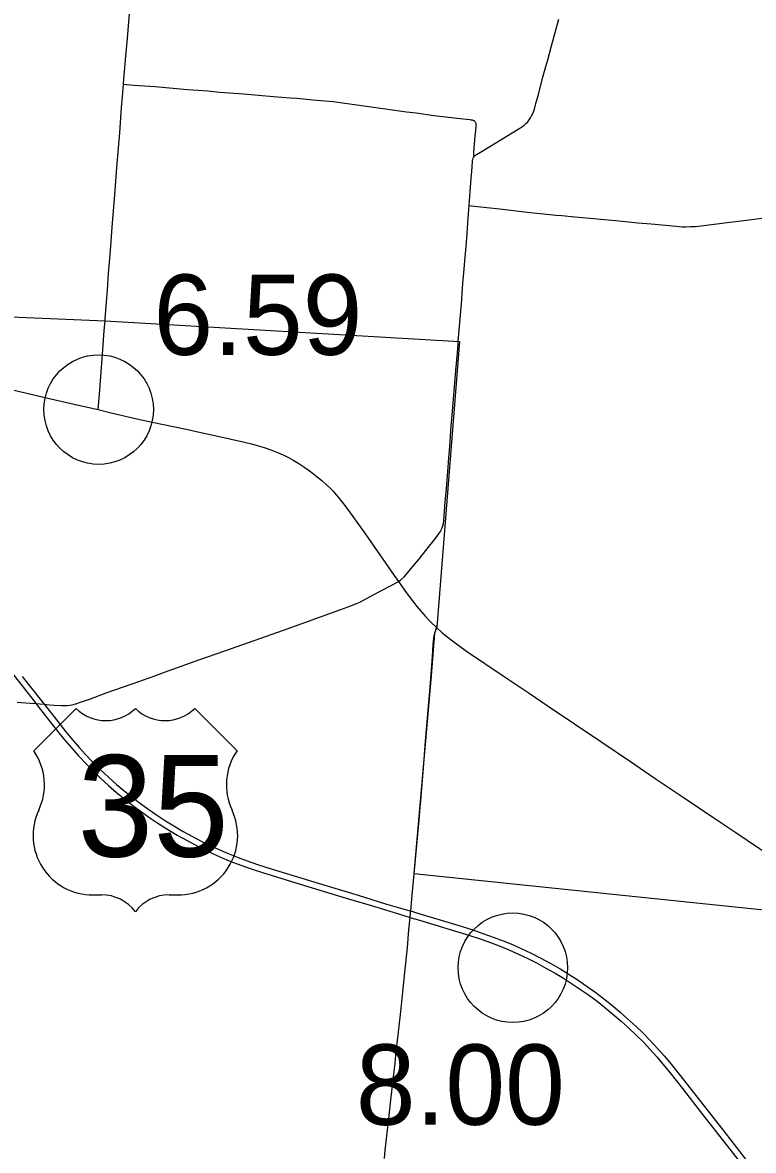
# Model space of a CAD drawing. Extents: x 1597222 to 1925846, y 496284 to 911751.
# Drawn here: x 1667359 to 1677369, y 576766 to 592215 of the extents above; entities that cross this region are included whole.
import ezdxf

# ---------------------------------------------------------------- set-up
doc = ezdxf.new("R2010")
doc.units = 0
for name, color, linetype in [('Default', 7, 'Continuous'), ('GM_X_County_Road', 7, 'Continuous'), ('GM_X_State_Route', 7, 'Continuous'), ('GM_X_Township', 7, 'Continuous'), ('GM_X_Township_Road', 7, 'Continuous'), ('GM_X_US_Route', 7, 'Continuous'), ('GM_X_US_Shield', 7, 'Continuous')]:
    doc.layers.add(name, color=color, linetype=linetype)

msp = doc.modelspace()

# ---------------------------------------------------------------- linework, layer by layer
at = {"layer": 'Default'}
for centre in [(1668401, 586914), (1668401, 586914), (1674074, 579269)]:
    msp.add_circle(centre, 750, dxfattribs=at)
at = {"layer": 'GM_X_County_Road'}
for points in [[(1673543, 590381), (1673551, 590389), (1673561, 590398), (1673574, 590408), (1673631, 590442), (1673841, 590569), (1674149, 590757), (1674204, 590793), (1674230, 590812), (1674254, 590834), (1674277, 590857), (1674297, 590882), (1674315, 590909), (1674331, 590937), (1674352, 590981), (1674369, 591027), (1674391, 591105), (1674424, 591232), (1674481, 591455), (1674498, 591518), (1674525, 591613), (1674552, 591707), (1674605, 591897), (1674704, 592261)], [(1673477, 589710), (1673491, 589899), (1673503, 590079), (1673510, 590177), (1673515, 590242), (1673520, 590308), (1673521, 590325), (1673525, 590341), (1673530, 590358), (1673535, 590369), (1673543, 590381)], [(1673326, 587848), (1673339, 588003), (1673370, 588363), (1673391, 588641), (1673407, 588837), (1673417, 588951), (1673433, 589147), (1673447, 589327), (1673459, 589474), (1673473, 589654), (1673477, 589710)], [(1673477, 589710), (1673508, 589707), (1673718, 589682), (1673897, 589662), (1674272, 589620), (1674582, 589588), (1674663, 589579), (1674744, 589572), (1674923, 589555), (1675135, 589535), (1675331, 589518), (1675478, 589504), (1675657, 589486), (1675787, 589473), (1675967, 589457), (1676309, 589426), (1676391, 589419), (1676440, 589418), (1676506, 589420), (1676572, 589424), (1676653, 589433), (1677011, 589478), (1677239, 589505), (1677483, 589534)], [(1673117, 585324), (1673123, 585356), (1673127, 585388), (1673148, 585650), (1673163, 585830), (1673187, 586124), (1673198, 586254), (1673206, 586352), (1673215, 586467), (1673226, 586630), (1673242, 586843), (1673260, 587055), (1673292, 587448), (1673314, 587693), (1673323, 587811), (1673326, 587848)], [(1668393, 586915), (1668573, 586871), (1668925, 586789), (1669133, 586744), (1669598, 586644), (1669759, 586610), (1670031, 586550), (1670400, 586469), (1670495, 586446), (1670574, 586424), (1670668, 586395), (1670760, 586362), (1670852, 586326), (1670927, 586294), (1671000, 586258), (1671072, 586218), (1671142, 586176), (1671224, 586121), (1671304, 586064), (1671395, 585995), (1671458, 585943), (1671519, 585888), (1671566, 585842), (1671611, 585795), (1671676, 585721), (1671738, 585646), (1671788, 585581), (1671884, 585448), (1672054, 585206), (1672262, 584912), (1672450, 584642), (1672486, 584592), (1672509, 584558)], [(1672509, 584558), (1672530, 584571), (1672546, 584585), (1672585, 584625), (1672706, 584765), (1672783, 584858), (1672851, 584942), (1672913, 585023), (1672990, 585123), (1673036, 585182), (1673066, 585221), (1673086, 585251), (1673094, 585265), (1673108, 585294), (1673117, 585324)], [(1667286, 582907), (1667465, 582892), (1667542, 582886), (1667597, 582882), (1667655, 582878), (1667727, 582872), (1667792, 582867), (1667891, 582862), (1667941, 582861), (1667974, 582862), (1668007, 582866), (1668039, 582872), (1668087, 582885), (1668150, 582905), (1668289, 582954), (1668505, 583033), (1668860, 583159), (1669169, 583269), (1669354, 583335), (1669787, 583489), (1670127, 583609), (1670529, 583750), (1670931, 583893), (1671441, 584074), (1671703, 584170), (1671857, 584226), (1671933, 584256), (1671978, 584277), (1672037, 584307), (1672181, 584385), (1672398, 584501), (1672509, 584558)], [(1672509, 584558), (1672541, 584513), (1672601, 584428), (1672698, 584295), (1672758, 584217), (1672821, 584142), (1672876, 584080), (1672945, 584009), (1673027, 583930), (1673029, 583928)], [(1672802, 581413), (1672814, 581553), (1672832, 581782), (1672845, 581946), (1672859, 582126), (1672879, 582371), (1672916, 582796), (1672938, 583057), (1672948, 583172), (1672962, 583351), (1672974, 583534), (1672979, 583616), (1672983, 583699), (1672986, 583746), (1672991, 583782), (1672997, 583815), (1673006, 583851), (1673018, 583890), (1673029, 583928)], [(1673029, 583928), (1673100, 583863), (1673163, 583810), (1673227, 583759), (1673320, 583691), (1673454, 583596), (1673943, 583265), (1674148, 583129), (1674297, 583028), (1674556, 582853), (1675277, 582368), (1675684, 582092), (1676024, 581863), (1676392, 581615), (1676813, 581331), (1676990, 581211), (1677126, 581120), (1677453, 580900), (1677630, 580782), (1677766, 580690), (1678105, 580460), (1678419, 580251), (1678704, 580058), (1678915, 579914)], [(1672722, 580557), (1672772, 581096), (1672795, 581341), (1672802, 581413)], [(1672315, 576658), (1672326, 576772), (1672350, 576968), (1672381, 577245), (1672403, 577457), (1672433, 577734), (1672460, 577962), (1672478, 578125), (1672507, 578386), (1672544, 578712), (1672569, 578941), (1672596, 579202), (1672629, 579544), (1672651, 579789), (1672667, 579959), (1672672, 580018), (1672675, 580047), (1672695, 580263), (1672718, 580508), (1672722, 580557)]]:
    msp.add_lwpolyline(points, dxfattribs=at)
at = {"layer": 'GM_X_State_Route'}
for points in [[(1668393, 586915), (1668411, 587126), (1668458, 587731), (1668478, 587999), (1668488, 588129), (1668490, 588156), (1668508, 588385), (1668521, 588548), (1668537, 588777), (1668562, 589088), (1668587, 589415), (1668622, 589856), (1668652, 590232), (1668674, 590494), (1668690, 590706), (1668716, 591050), (1668728, 591197), (1668742, 591371), (1668748, 591442), (1668774, 591753), (1668794, 591998), (1668841, 592570)], [(1662370, 588315), (1662657, 588245), (1663024, 588158), (1663551, 588037), (1663664, 588011), (1663967, 587939), (1664382, 587843), (1664654, 587779), (1665532, 587576), (1666267, 587405), (1666682, 587309), (1667162, 587198), (1667417, 587138), (1667705, 587072), (1668168, 586964), (1668393, 586915)]]:
    msp.add_lwpolyline(points, dxfattribs=at)
at = {"layer": 'GM_X_Township'}
msp.add_lwpolyline([(1640772, 591419), (1641501, 591232), (1645959, 590087), (1646099, 590051), (1651332, 588679), (1652031, 588630), (1654972, 588478), (1658610, 588362), (1660153, 588344), (1660296, 588340), (1662371, 588281), (1662472, 588280), (1663570, 588267), (1665903, 588241), (1668490, 588131), (1673343, 587846), (1673034, 583935), (1673000, 583850), (1672955, 583266), (1672719, 580558), (1678923, 579915)], dxfattribs=at)
at = {"layer": 'GM_X_Township_Road'}
msp.add_lwpolyline([(1668742, 591371), (1668784, 591368), (1668882, 591360), (1669176, 591338), (1669618, 591300), (1669765, 591288), (1669896, 591278), (1670059, 591264), (1670386, 591238), (1670795, 591204), (1671024, 591185), (1671122, 591178), (1671334, 591159), (1671498, 591145), (1671612, 591134), (1671710, 591122), (1671905, 591094), (1672197, 591051), (1672424, 591020), (1672619, 590993), (1672750, 590977), (1672993, 590944), (1673156, 590924), (1673270, 590911), (1673352, 590902), (1673483, 590886), (1673499, 590884), (1673515, 590881), (1673524, 590878), (1673532, 590876), (1673539, 590873), (1673547, 590867), (1673554, 590861), (1673559, 590855), (1673563, 590847), (1673566, 590839), (1673568, 590831), (1673569, 590821), (1673569, 590809), (1673567, 590794), (1673562, 590739), (1673555, 590657), (1673535, 590444), (1673534, 590411), (1673535, 590399), (1673538, 590391), (1673543, 590381)], dxfattribs=at)
at = {"layer": 'GM_X_US_Route'}
for points in [[(1667202, 583320), (1667516, 582920), (1667542, 582886), (1667668, 582726), (1667819, 582532), (1667933, 582392), (1668028, 582279), (1668127, 582170), (1668228, 582062), (1668320, 581969), (1668427, 581867), (1668536, 581767), (1668647, 581671), (1668735, 581598), (1668851, 581506), (1668969, 581417), (1669089, 581332), (1669212, 581250), (1669336, 581171), (1669477, 581087), (1669605, 581014), (1669721, 580952), (1669853, 580886), (1669971, 580830), (1670091, 580776), (1670212, 580726), (1670350, 580673), (1670489, 580623), (1670645, 580572), (1671162, 580413), (1671790, 580224), (1672120, 580124), (1672434, 580029), (1672667, 579959), (1672843, 579905), (1673172, 579805), (1673486, 579709), (1673642, 579658), (1673766, 579614), (1673888, 579567), (1674010, 579517), (1674160, 579450), (1674279, 579395), (1674396, 579335), (1674527, 579265), (1674655, 579193), (1674768, 579125), (1674893, 579046), (1675002, 578973), (1675109, 578897), (1675228, 578809), (1675331, 578727), (1675445, 578634), (1675557, 578537), (1675654, 578449), (1675762, 578347), (1675866, 578243), (1675956, 578147), (1676044, 578050), (1676130, 577950), (1676224, 577836), (1676396, 577616), (1676628, 577319), (1677325, 576427)], [(1667354, 583260), (1667618, 582925), (1667655, 582878), (1667840, 582641), (1667953, 582500), (1668047, 582386), (1668133, 582287), (1668221, 582190), (1668313, 582095), (1668417, 581991), (1668537, 581878), (1668647, 581780), (1668747, 581695), (1668837, 581623), (1668954, 581533), (1669073, 581446), (1669194, 581362), (1669318, 581281), (1669430, 581212), (1669557, 581137), (1669686, 581065), (1669803, 581004), (1669920, 580946), (1670040, 580891), (1670175, 580832), (1670312, 580777), (1670436, 580732), (1670575, 580684), (1670763, 580624), (1671124, 580515), (1671407, 580429), (1671956, 580263), (1672332, 580145), (1672426, 580117), (1672521, 580090), (1672663, 580050), (1672675, 580047), (1672741, 580026), (1673321, 579850), (1673525, 579787), (1673665, 579740), (1673819, 579685), (1673957, 579631), (1674078, 579581), (1674198, 579528), (1674316, 579471), (1674447, 579404), (1674592, 579327), (1674720, 579254), (1674832, 579185), (1674970, 579097), (1675092, 579014), (1675198, 578937), (1675315, 578848), (1675443, 578746), (1675544, 578662), (1675642, 578575), (1675763, 578464), (1675857, 578372), (1675960, 578267), (1676060, 578159), (1676147, 578061), (1676242, 577948), (1676366, 577795), (1676598, 577497), (1676981, 577006), (1677293, 576604)]]:
    msp.add_lwpolyline(points, dxfattribs=at)
at = {"layer": 'GM_X_US_Shield'}
for p, q in [((1668092, 582821), (1667512, 582240)), ((1670296, 582240), (1669716, 582821)), ((1668324, 580268), (1668440, 580268)), ((1669368, 580268), (1669484, 580268))]:
    msp.add_line(p, q, dxfattribs=at)
for centre, radius, start, end in [((1668498, 583235), 580, 225.573, 314.427), ((1669310, 583235), 580, 225.573, 314.427), ((1666847, 581775), 812, 334.5471, 35.0009), ((1670962, 581775), 812, 144.9991, 205.4529), ((1668315, 581080), 812, 154.8319, 270.6383), ((1669493, 581080), 812, 269.3617, 25.1681), ((1668440, 579688), 580, 36.8699, 90), ((1669368, 579688), 580, 90, 143.1301)]:
    msp.add_arc(centre, radius, start, end, dxfattribs=at)

# ---------------------------------------------------------------- texts
at = {"layer": 'Default'}
for s, p in [('6.59', (1669151, 587664)), ('6.59', (1669151, 587664)), ('8.00', (1671923, 577118))]:
    msp.add_text(s, height=1100, dxfattribs=at).set_placement(p)
at = {"layer": 'GM_X_US_Shield'}
msp.add_text('35', height=1392.2, dxfattribs=at).set_placement((1668112, 580790))

doc.saveas('drawing.dxf')
